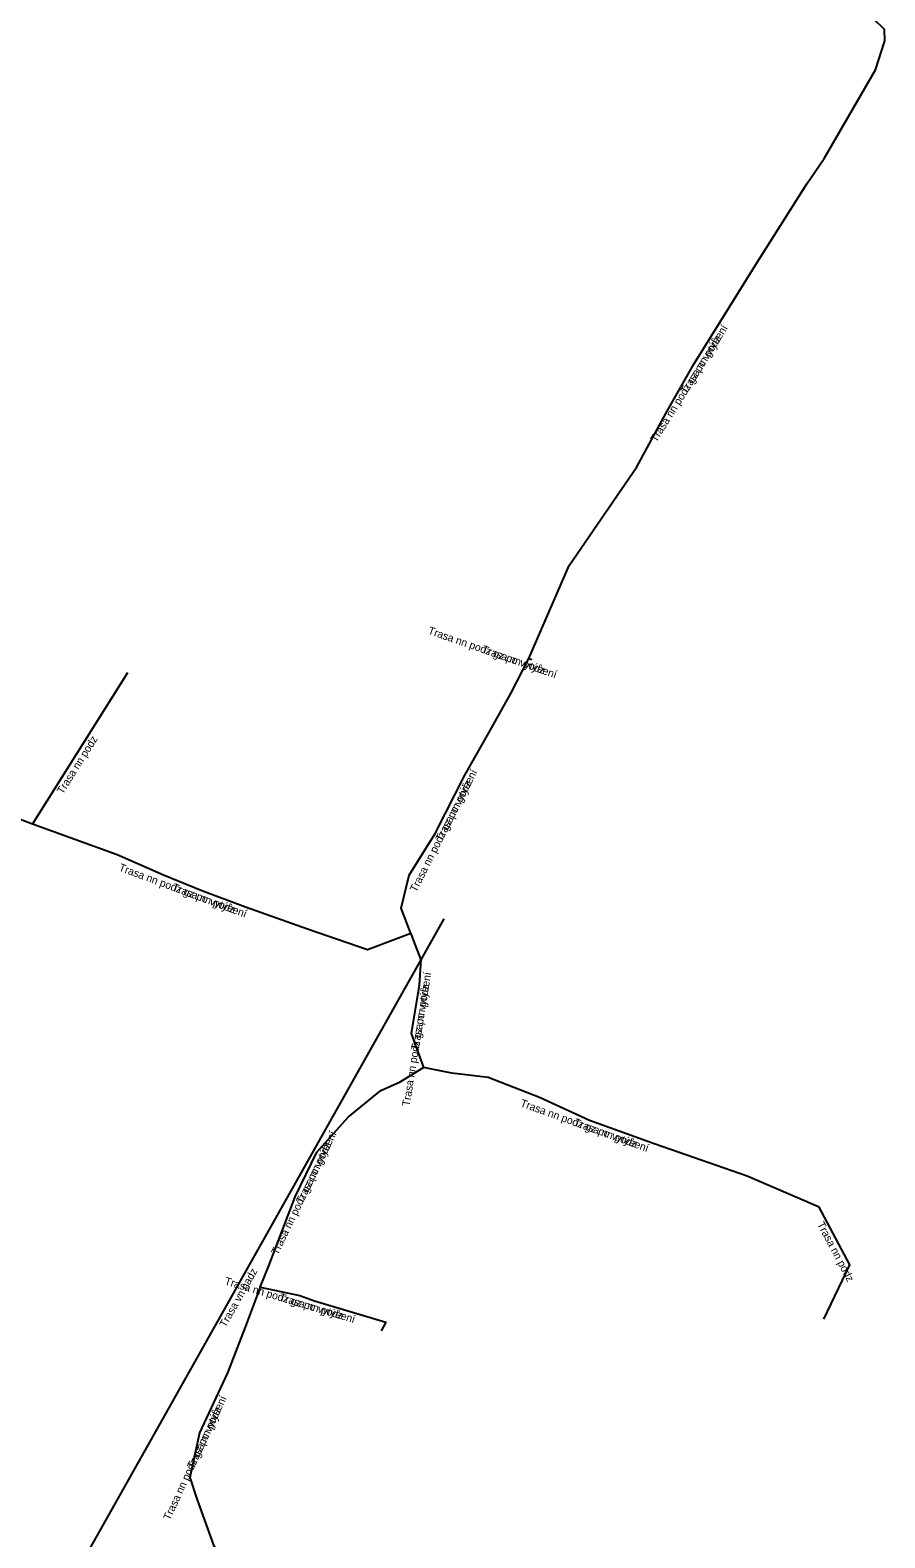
# Model space of a CAD drawing. Extents: x -703240 to -702678, y -1007635 to -1007322.
# Drawn here: x -703120.1 to -703064.8, y -1007473.5 to -1007375.9 of the extents above; entities that cross this region are included whole.
import ezdxf

# ---------------------------------------------------------------- set-up
doc = ezdxf.new("R2010")
doc.units = 0
for name, color, linetype in [('Popiskový text - Ostatní atributy Trasy', 7, 'Continuous'), ('Spojnice NN', 7, 'Continuous'), ('Spojnice VN', 7, 'Continuous')]:
    doc.layers.add(name, color=color, linetype=linetype)

msp = doc.modelspace()

# ---------------------------------------------------------------- linework, layer by layer
at = {"layer": 'Spojnice NN'}
for points in [[(-703064.75, -1007376.6), (-703064.77, -1007375.86), (-703065.48, -1007375.17), (-703072.35, -1007372.56), (-703073.27, -1007372.03)], [(-703087.8, -1007416.56), (-703085.18, -1007410.55), (-703080.81, -1007404.16), (-703078.93, -1007400.71), (-703077.12, -1007397.51), (-703073.1, -1007391.08), (-703069.8, -1007385.85), (-703068.68, -1007384.21), (-703065.36, -1007378.47), (-703064.75, -1007376.6)], [(-703087.8, -1007416.56), (-703085.18, -1007410.55), (-703080.81, -1007404.16), (-703078.93, -1007400.71), (-703077.12, -1007397.51), (-703073.1, -1007391.08), (-703069.8, -1007385.85), (-703068.68, -1007384.21), (-703065.36, -1007378.47), (-703064.75, -1007376.6)], [(-703095.44, -1007434.35), (-703096.06, -1007432.72), (-703095.55, -1007430.57), (-703093.87, -1007427.88), (-703091.95, -1007424.1), (-703090.38, -1007421.37), (-703088.96, -1007418.83), (-703087.8, -1007416.56)], [(-703095.44, -1007434.35), (-703096.06, -1007432.72), (-703095.55, -1007430.57), (-703093.87, -1007427.88), (-703091.95, -1007424.1), (-703090.38, -1007421.37), (-703088.96, -1007418.83), (-703087.8, -1007416.56)], [(-703087.8, -1007416.56), (-703087.6, -1007416.63)], [(-703087.8, -1007416.56), (-703087.6, -1007416.63)], [(-703119.93, -1007427.27), (-703113.759, -1007417.473)], [(-703119.93, -1007427.27), (-703124.86, -1007425.43), (-703129.96, -1007423.61), (-703135.71, -1007421.33), (-703141.79, -1007419.13), (-703142.2, -1007418.9)], [(-703119.93, -1007427.27), (-703124.86, -1007425.43), (-703129.96, -1007423.61), (-703135.71, -1007421.33), (-703141.79, -1007419.13), (-703142.2, -1007418.9)], [(-703095.44, -1007434.35), (-703096.4, -1007434.73), (-703098.25, -1007435.41), (-703102.12, -1007434.07), (-703106.14, -1007432.65), (-703108.96, -1007431.6), (-703111.46, -1007430.57), (-703114.46, -1007429.26), (-703119.93, -1007427.27)], [(-703095.44, -1007434.35), (-703096.4, -1007434.73), (-703098.25, -1007435.41), (-703102.12, -1007434.07), (-703106.14, -1007432.65), (-703108.96, -1007431.6), (-703111.46, -1007430.57), (-703114.46, -1007429.26), (-703119.93, -1007427.27)], [(-703095.44, -1007434.35), (-703095.26, -1007434.83), (-703094.8, -1007436.06), (-703094.9, -1007437.69), (-703095.41, -1007440.83), (-703094.62, -1007443.03)], [(-703095.44, -1007434.35), (-703095.26, -1007434.83), (-703094.8, -1007436.06), (-703094.9, -1007437.69), (-703095.41, -1007440.83), (-703094.62, -1007443.03)], [(-703105.19, -1007457.24), (-703104.63, -1007455.86), (-703102.93, -1007451.38), (-703101.53, -1007448.49), (-703099.5, -1007446.24), (-703097.38, -1007444.5), (-703096.13, -1007443.95), (-703094.62, -1007443.03)], [(-703105.19, -1007457.24), (-703104.63, -1007455.86), (-703102.93, -1007451.38), (-703101.53, -1007448.49), (-703099.5, -1007446.24), (-703097.38, -1007444.5), (-703096.13, -1007443.95), (-703094.62, -1007443.03)], [(-703069, -1007452.05), (-703073.67, -1007450.06), (-703079.62, -1007447.99), (-703083.87, -1007446.46), (-703087.11, -1007444.96), (-703090.43, -1007443.66), (-703092.78, -1007443.39), (-703094.62, -1007443.03)], [(-703069, -1007452.05), (-703073.67, -1007450.06), (-703079.62, -1007447.99), (-703083.87, -1007446.46), (-703087.11, -1007444.96), (-703090.43, -1007443.66), (-703092.78, -1007443.39), (-703094.62, -1007443.03)], [(-703068.695, -1007459.295), (-703067.024, -1007455.793), (-703069, -1007452.05)], [(-703105.19, -1007457.24), (-703106.16, -1007459.83), (-703107.31, -1007462.78), (-703109.11, -1007466.66), (-703109.74, -1007469.54), (-703109.29, -1007470.92), (-703108.22, -1007473.93), (-703107.73, -1007474.7)], [(-703105.19, -1007457.24), (-703106.16, -1007459.83), (-703107.31, -1007462.78), (-703109.11, -1007466.66), (-703109.74, -1007469.54), (-703109.29, -1007470.92), (-703108.22, -1007473.93), (-703107.73, -1007474.7)], [(-703105.19, -1007457.24), (-703102.62, -1007457.78), (-703101.67, -1007458.12), (-703097.05, -1007459.5), (-703097.36, -1007460.05)], [(-703105.19, -1007457.24), (-703102.62, -1007457.78), (-703101.67, -1007458.12), (-703097.05, -1007459.5), (-703097.36, -1007460.05)]]:
    msp.add_lwpolyline(points, dxfattribs=at)
at = {"layer": 'Spojnice VN'}
msp.add_lwpolyline([(-703119.62, -1007480.22), (-703093.279, -1007433.414)], dxfattribs=at)

# ---------------------------------------------------------------- texts
at = {"layer": 'Popiskový text - Ostatní atributy Trasy'}
for s, rotation, p in [('Trasa nn podz gz po vytýèení', 57.98661, (-703079.542, -1007402.61)), ('Trasa nn podz', 57.98661, (-703077.589, -1007399.485)), ('Trasa nn podz gz po vytýèení', 340.70995, (-703094.364, -1007414.952)), ('Trasa nn podz', 340.70995, (-703090.886, -1007416.169)), ('Trasa nn podz', 57.79372, (-703117.972, -1007425.382)), ('Trasa nn podz gz po vytýèení', 63.07232, (-703095.088, -1007431.715)), ('Trasa nn podz', 63.07232, (-703093.42, -1007428.43)), ('Trasa nn podz gz po vytýèení', 339.57767, (-703114.384, -1007430.274)), ('Trasa nn podz', 339.57767, (-703110.931, -1007431.56)), ('Trasa nn podz gz po vytýèení', 80.77456, (-703095.519, -1007445.555)), ('Trasa nn podz', 80.77456, (-703094.928, -1007441.918)), ('Trasa nn podz gz po vytýèení', 340.20112, (-703088.394, -1007445.522)), ('Trasa nn podz', 340.20112, (-703084.927, -1007446.77)), ('Trasa nn podz gz po vytýèení', 64.1531, (-703104.052, -1007455.186)), ('Trasa nn podz', 64.1531, (-703102.445, -1007451.87)), ('Trasa nn podz', 297.83041, (-703069.151, -1007453.157)), ('Trasa vn nadz', 60.63051, (-703107.427, -1007459.879)), ('Trasa nn podz gz po vytýèení', 343.36905, (-703107.532, -1007457.047)), ('Trasa nn podz', 343.36905, (-703104.002, -1007458.102)), ('Trasa nn podz gz po vytýèení', 65.11259, (-703111.038, -1007472.359)), ('Trasa nn podz', 65.11259, (-703109.487, -1007469.017))]:
    msp.add_text(s, height=0.5, rotation=rotation, dxfattribs=at).set_placement(p)

doc.saveas('drawing.dxf')
